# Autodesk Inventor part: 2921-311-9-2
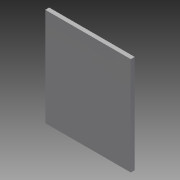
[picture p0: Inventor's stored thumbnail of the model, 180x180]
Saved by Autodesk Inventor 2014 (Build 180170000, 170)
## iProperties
Company: NHTSA/VRTC
Created: 2012-02
Part Number: 2921-311-9-2
Project: CHILD SIDE IMPACT SLED
Material: Steel
Description: SHT. #16 Ga. x 38.1 (1.5") x 33.2 (1.31")
Document SubType Name: Modeling
Designer: Dave Walker
Mass: 15.0823 g
Surface Area: 27.4644 cm^2
Volume: 1.92131 cm^3
Density: 7.85 g/cm^3
Appearance: Steel
Title: BENCH FRAME TUBE #8 CAP #1
Subject: Child Side Impact Sled
Author: Dave Walker
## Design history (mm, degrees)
sketch "Sketch1"
  geometry: L1 (-16.6, 19.05)-(16.6, 19.05); L2 (16.6, 19.05)-(16.6, -19.05); L3 (16.6, -19.05)-(-16.6, -19.05); L4 (-16.6, -19.05)-(-16.6, 19.05); L5 (0, 26.67)-(0, -26.67) reference; L6 (-23.24, 0)-(23.24, 0) reference
  constraints: 8 end point, 2 parallel, 1 horizontal, 1 perpendicular, 2 other
  dimensions: "d0" = 38.1 distance of L3.end L1.start; "d1" = 33.2 distance of L2.end L3.end
extrude "Extrusion1" new body sketch "Sketch1" distance "d2" = 1.51892; taper "d3" = 0 deg
body "Solid1"
